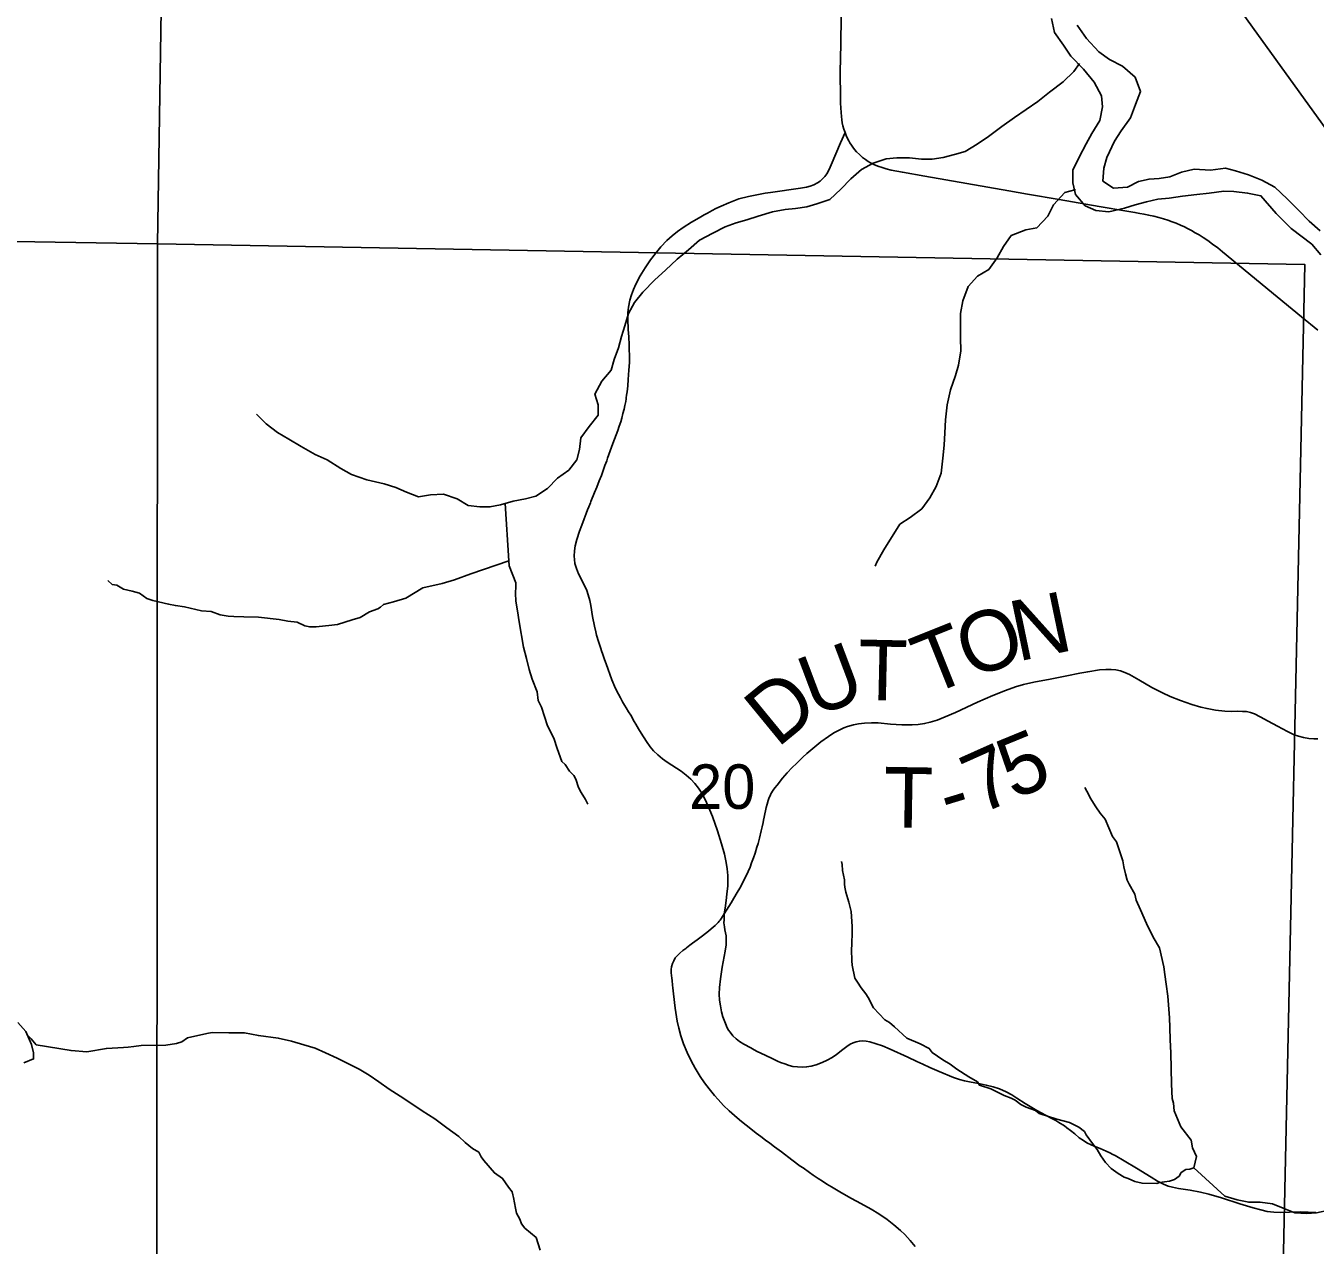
# Model space of a CAD drawing. Extents: x 0 to 34, y 0 to 22.
# Drawn here: x 5.516 to 6.729, y 14.708 to 15.855 of the extents above; entities that cross this region are included whole.
import ezdxf

# ---------------------------------------------------------------- set-up
doc = ezdxf.new("R2010")
doc.units = 0
for name, color, linetype in [('GM_X_Major_River', 7, 'Continuous'), ('GM_X_Minor_River', 7, 'Continuous'), ('GM_X_Rail_Line', 7, 'Continuous'), ('GM_X_Section', 7, 'Continuous'), ('GM_X_Section_Text', 7, 'Continuous'), ('GM_X_State_Route', 7, 'Continuous'), ('GM_X_Township_Road', 7, 'Continuous'), ('GM_X_Township_Road_Text', 7, 'Continuous')]:
    doc.layers.add(name, color=color, linetype=linetype)

msp = doc.modelspace()

# ---------------------------------------------------------------- linework, layer by layer
at = {"layer": 'GM_X_Major_River'}
for points in [[(6.4806, 15.8617), (6.4834, 15.8485), (6.4919, 15.8364), (6.4989, 15.8263), (6.5108, 15.8139), (6.5208, 15.8016), (6.5278, 15.7888), (6.5287, 15.7785), (6.5262, 15.7656), (6.5188, 15.7534), (6.5132, 15.7438), (6.5066, 15.7312), (6.5007, 15.719), (6.5009, 15.7069), (6.5033, 15.6959), (6.5125, 15.6854), (6.5224, 15.681), (6.5346, 15.6796), (6.5493, 15.6832), (6.5595, 15.6864), (6.5701, 15.6892), (6.5807, 15.6916), (6.5913, 15.6925), (6.6041, 15.6946), (6.6174, 15.6959), (6.6291, 15.6972), (6.6428, 15.6993), (6.6522, 15.699), (6.6652, 15.6973), (6.6777, 15.6948), (6.6922, 15.678), (6.7061, 15.6641), (6.7255, 15.6493), (6.7341, 15.6393)], [(6.7335, 15.6618), (6.7231, 15.6708), (6.7135, 15.6809), (6.7024, 15.6918), (6.6909, 15.703), (6.6786, 15.7096), (6.6661, 15.7144), (6.6539, 15.7184), (6.6444, 15.7209), (6.6304, 15.7188), (6.6148, 15.7198), (6.6031, 15.717), (6.5921, 15.7126), (6.5819, 15.711), (6.5725, 15.7105), (6.5626, 15.7084), (6.5521, 15.703), (6.5392, 15.7021), (6.5289, 15.7087), (6.5299, 15.7209), (6.5328, 15.7308), (6.5401, 15.7461), (6.5464, 15.756), (6.555, 15.7683), (6.5598, 15.7808), (6.5645, 15.793), (6.5594, 15.8063), (6.5475, 15.8167), (6.5353, 15.823), (6.5253, 15.8301), (6.5138, 15.8428), (6.5049, 15.8552)]]:
    msp.add_lwpolyline(points, dxfattribs=at)
at = {"layer": 'GM_X_Minor_River'}
for points in [[(6.5072, 15.8192), (6.5018, 15.8116), (6.4916, 15.8021), (6.4787, 15.7923), (6.4678, 15.7836), (6.4459, 15.7684), (6.4339, 15.7601), (6.4214, 15.7507), (6.4109, 15.7434), (6.3996, 15.7366), (6.3896, 15.7335), (6.3789, 15.7309), (6.3686, 15.7293), (6.3583, 15.7293), (6.347, 15.7305), (6.3352, 15.7305), (6.3253, 15.7297), (6.313, 15.7256), (6.3021, 15.7195), (6.2919, 15.7108), (6.2825, 15.7009), (6.2723, 15.6913), (6.2599, 15.6872), (6.2504, 15.6845), (6.24, 15.683), (6.2301, 15.6818), (6.2183, 15.6796), (6.2048, 15.6755), (6.1941, 15.6721), (6.1841, 15.6694), (6.1737, 15.6656), (6.1621, 15.6595), (6.1497, 15.6531), (6.1391, 15.644), (6.1286, 15.6353), (6.1176, 15.625), (6.1074, 15.6159), (6.0963, 15.6041), (6.0884, 15.5945), (6.0827, 15.5841), (6.0792, 15.5724), (6.0762, 15.5623), (6.0732, 15.5517), (6.0694, 15.5409), (6.0664, 15.5307), (6.0577, 15.5204), (6.0511, 15.5081), (6.0542, 15.4981), (6.0543, 15.4886), (6.0459, 15.4779), (6.0379, 15.4671), (6.0368, 15.4561), (6.0342, 15.4464), (6.0266, 15.4368), (6.0161, 15.4291), (6.0066, 15.4196), (5.9957, 15.4124), (5.9858, 15.4097), (5.9743, 15.4075), (5.9624, 15.4041), (5.9524, 15.4021), (5.9429, 15.4021), (5.932, 15.4036), (5.9215, 15.4097), (5.9088, 15.414), (5.8966, 15.4136), (5.8851, 15.4117), (5.8739, 15.4159), (5.8638, 15.4205), (5.8529, 15.4239), (5.8367, 15.4275), (5.822, 15.4326), (5.812, 15.4383), (5.7993, 15.4463), (5.7881, 15.4513), (5.7747, 15.459), (5.7632, 15.4658), (5.7524, 15.4723), (5.742, 15.4803), (5.7328, 15.4893)], [(6.5032, 15.7005), (6.5028, 15.7003), (6.4933, 15.698), (6.4826, 15.6862), (6.4773, 15.6757), (6.467, 15.6647), (6.4567, 15.6628), (6.4428, 15.6576), (6.4356, 15.6472), (6.4295, 15.6364), (6.4219, 15.6256), (6.4111, 15.6192), (6.4024, 15.6096), (6.3974, 15.5961), (6.395, 15.584), (6.395, 15.5726), (6.395, 15.5612), (6.3953, 15.5491), (6.3933, 15.5355), (6.3903, 15.5257), (6.3857, 15.5122), (6.3825, 15.4982), (6.3809, 15.4842), (6.3805, 15.4717), (6.3797, 15.4603), (6.3785, 15.4479), (6.3769, 15.4339), (6.3722, 15.4215), (6.3662, 15.4107), (6.3586, 15.4003), (6.3477, 15.3923), (6.3379, 15.3858), (6.323, 15.3617), (6.3165, 15.3501), (6.3149, 15.3464)], [(5.9668, 15.4055), (5.9701, 15.3515), (5.9706, 15.3466), (5.9766, 15.3307), (5.9766, 15.3273), (5.9764, 15.3209), (5.9769, 15.3136), (5.9782, 15.3045), (5.9799, 15.2939), (5.9841, 15.2701), (5.9869, 15.2595), (5.9894, 15.2493), (5.9922, 15.2402), (5.9969, 15.2281), (5.9978, 15.2201), (6.001, 15.2137), (6.0066, 15.1963), (6.0125, 15.1847), (6.0157, 15.1748), (6.0201, 15.1627), (6.0232, 15.1597), (6.0271, 15.1537), (6.0313, 15.1496), (6.0333, 15.1462), (6.0357, 15.1383), (6.0381, 15.1334), (6.0424, 15.127), (6.0444, 15.1224)], [(5.9701, 15.3515), (5.9343, 15.3392), (5.9192, 15.3336), (5.9075, 15.33), (5.8893, 15.3259), (5.8732, 15.3162), (5.8615, 15.313), (5.8524, 15.3105), (5.8494, 15.3078), (5.8468, 15.3063), (5.8392, 15.3035), (5.8302, 15.298), (5.8227, 15.296), (5.8091, 15.2916), (5.8007, 15.2907), (5.7916, 15.2898), (5.789, 15.2894), (5.7829, 15.2893), (5.7783, 15.2904), (5.7711, 15.2937), (5.7623, 15.2947), (5.754, 15.2961), (5.7346, 15.2984), (5.7209, 15.2986), (5.7114, 15.2992), (5.7061, 15.2995), (5.6985, 15.3005), (5.69, 15.3038), (5.6809, 15.3044), (5.6649, 15.308), (5.6565, 15.3094), (5.6501, 15.3108), (5.6352, 15.314), (5.6295, 15.3161), (5.6226, 15.321), (5.6157, 15.3228), (5.6077, 15.3249), (5.6012, 15.3286), (5.597, 15.3293), (5.593, 15.3328)], [(6.6147, 14.7804), (6.6172, 14.7911), (6.6133, 14.7994), (6.612, 14.8066), (6.6023, 14.819), (6.596, 14.8341), (6.5955, 14.8413), (6.5943, 14.8458), (6.5936, 14.8591), (6.5931, 14.8887), (6.5925, 14.9009), (6.592, 14.9123), (6.5918, 14.9214), (6.5903, 14.9419), (6.5886, 14.9532), (6.5873, 14.9623), (6.5864, 14.9695), (6.5823, 14.9873), (6.5764, 14.9975), (6.5701, 15.0103), (6.5646, 15.0231), (6.5603, 15.0322), (6.559, 15.0379), (6.5539, 15.0473), (6.552, 15.0511), (6.5504, 15.0571), (6.5487, 15.0635), (6.5479, 15.0692), (6.5419, 15.087), (6.538, 15.0922), (6.5312, 15.1085), (6.5266, 15.1141), (6.5223, 15.1201), (6.5172, 15.1284), (6.5157, 15.1314), (6.5141, 15.1348), (6.5121, 15.1382)], [(6.2833, 15.0685), (6.2837, 15.0658), (6.2842, 15.0601), (6.2859, 15.0514), (6.2859, 15.0472), (6.2864, 15.0446), (6.2872, 15.0397), (6.29, 15.0302), (6.2921, 15.0215), (6.2931, 15.0075), (6.2932, 15.0025), (6.293, 14.9904), (6.2927, 14.9858), (6.2929, 14.9752), (6.2933, 14.971), (6.2958, 14.9589), (6.2982, 14.9551), (6.3017, 14.9499), (6.3059, 14.9442), (6.3083, 14.9408), (6.3134, 14.931), (6.3238, 14.9198), (6.3284, 14.9172), (6.333, 14.9131), (6.3446, 14.9023), (6.3572, 14.8972), (6.3657, 14.8927), (6.3684, 14.889), (6.3784, 14.8819), (6.3853, 14.8778), (6.3918, 14.8734), (6.403, 14.866), (6.411, 14.8612), (6.413, 14.8581), (6.4236, 14.8549), (6.4363, 14.8486), (6.4428, 14.8461), (6.4466, 14.8442), (6.452, 14.8401), (6.457, 14.8376), (6.4658, 14.8343), (6.4692, 14.8317), (6.4856, 14.8262), (6.4978, 14.823), (6.5063, 14.8186), (6.5117, 14.8145), (6.5132, 14.8115), (6.5194, 14.8032), (6.5237, 14.7976), (6.5272, 14.7916), (6.5315, 14.7855), (6.5369, 14.7799), (6.5435, 14.7751), (6.5492, 14.7718), (6.5527, 14.7703), (6.5592, 14.7677), (6.566, 14.766), (6.5797, 14.7658), (6.5823, 14.7666), (6.5918, 14.7679), (6.5963, 14.7695), (6.6008, 14.7726), (6.6027, 14.776), (6.6072, 14.7788), (6.611, 14.7792), (6.6147, 14.7804)], [(5.514, 14.8793), (5.5231, 14.8829), (5.523, 14.8886), (5.521, 14.8965), (5.5158, 14.9086), (5.5081, 14.9172)], [(5.5171, 14.9056), (5.5209, 14.9018), (5.5255, 14.8962), (5.5583, 14.8907), (5.5731, 14.8894), (5.5916, 14.8927), (5.6076, 14.8937), (5.6121, 14.8938), (5.6174, 14.8946), (5.6242, 14.8955), (5.6474, 14.8959), (5.6576, 14.8975), (5.6625, 14.8991), (5.6678, 14.9026), (5.6859, 14.9067), (5.6912, 14.9076), (5.7068, 14.9074), (5.7216, 14.9073), (5.7345, 14.9048), (5.7532, 14.9025), (5.7658, 14.8996), (5.7772, 14.896), (5.7879, 14.8931), (5.7978, 14.8887), (5.8085, 14.8836), (5.8292, 14.8733), (5.8388, 14.8677), (5.8477, 14.8614), (5.8576, 14.8543), (5.868, 14.8477), (5.878, 14.8414), (5.8887, 14.8339), (5.9006, 14.8265), (5.9118, 14.818), (5.923, 14.8098), (5.9291, 14.8042), (5.9361, 14.7986), (5.9418, 14.7953), (5.9442, 14.7907), (5.9465, 14.7874), (5.9566, 14.7757), (5.9643, 14.7705), (5.9697, 14.7623), (5.9732, 14.7578), (5.974, 14.7551), (5.9744, 14.7525), (5.9765, 14.7426), (5.9773, 14.7377), (5.9805, 14.732), (5.9821, 14.7279), (5.9852, 14.7238), (5.996, 14.7148), (5.9996, 14.7031)], [(6.8402, 14.7225), (6.8294, 14.7267), (6.8189, 14.732), (6.8077, 14.7374), (6.798, 14.7427), (6.7878, 14.7449), (6.7757, 14.7453), (6.7642, 14.7435), (6.7524, 14.7416), (6.7417, 14.7405), (6.7302, 14.7382), (6.7207, 14.7374), (6.7097, 14.7382), (6.6988, 14.7424), (6.6887, 14.7465), (6.677, 14.7481), (6.6663, 14.7481), (6.6554, 14.7504), (6.6437, 14.7538), (6.6147, 14.7804)]]:
    msp.add_lwpolyline(points, dxfattribs=at)
at = {"layer": 'GM_X_Rail_Line'}
msp.add_lwpolyline([(6.5602, 16.0058), (6.7796, 15.7014)], dxfattribs=at)
at = {"layer": 'GM_X_Section'}
for points in [[(4.555, 16.6608), (5.6553, 16.6499), (5.6397, 15.6496), (4.5625, 15.6671), (4.5568, 16.3278)], [(4.5625, 15.6671), (5.6397, 15.6496), (5.6391, 14.6704), (4.5729, 14.6928), (4.5655, 15.3289)], [(5.6397, 15.6496), (6.7192, 15.6301), (6.698, 14.6582), (5.6391, 14.6704)]]:
    msp.add_lwpolyline(points, close=True, dxfattribs=at)
at = {"layer": 'GM_X_State_Route'}
msp.add_lwpolyline([(6.7312, 15.5684), (6.7158, 15.581), (6.6842, 15.607), (6.6611, 15.626), (6.6415, 15.6422), (6.6371, 15.6457), (6.6321, 15.6494), (6.6277, 15.6527), (6.6234, 15.6555), (6.6196, 15.658), (6.616, 15.6601), (6.6123, 15.6622), (6.6088, 15.664), (6.6057, 15.6656), (6.602, 15.6672), (6.598, 15.669), (6.5944, 15.6704), (6.5903, 15.6719), (6.5862, 15.6732), (6.5818, 15.6743), (6.577, 15.6755), (6.572, 15.6767), (6.5678, 15.6775), (6.5638, 15.6783), (6.5592, 15.6791), (6.5515, 15.6804), (6.5257, 15.6847), (6.4878, 15.6912), (6.4583, 15.6963), (6.4406, 15.6994), (6.3617, 15.7132), (6.3405, 15.7169), (6.3353, 15.7179), (6.3298, 15.719), (6.3253, 15.7201), (6.3214, 15.7213), (6.3172, 15.7227), (6.3136, 15.7244), (6.3105, 15.7259), (6.3083, 15.7272), (6.3057, 15.7289), (6.303, 15.7309), (6.3, 15.7336), (6.2974, 15.7361), (6.2955, 15.7384), (6.2939, 15.7404), (6.2925, 15.7423), (6.2911, 15.7445), (6.2899, 15.7466), (6.2888, 15.7487), (6.2876, 15.7515), (6.2865, 15.7542), (6.2854, 15.7575), (6.2845, 15.7605), (6.2839, 15.7634), (6.2834, 15.7663), (6.2831, 15.7694), (6.2827, 15.7731), (6.2824, 15.7774), (6.2822, 15.7818), (6.2821, 15.7866), (6.282, 15.8114), (6.2824, 15.8375), (6.2828, 15.8635)], dxfattribs=at)
at = {"layer": 'GM_X_Township_Road'}
for points in [[(6.1729, 15.0193), (6.1737, 15.0248), (6.1746, 15.0319), (6.1754, 15.038), (6.1761, 15.0456), (6.1761, 15.0555), (6.1757, 15.0616), (6.1747, 15.0677), (6.173, 15.0756), (6.1704, 15.0851), (6.1664, 15.0975), (6.1617, 15.111), (6.1578, 15.1208), (6.1547, 15.1276), (6.1517, 15.133), (6.1486, 15.1377), (6.1451, 15.142), (6.1413, 15.1461), (6.1371, 15.1498), (6.1322, 15.1535), (6.1192, 15.162), (6.1146, 15.1653), (6.1104, 15.1688), (6.1064, 15.1727), (6.1032, 15.1765), (6.0996, 15.1814), (6.0947, 15.1892), (6.0922, 15.1935), (6.0897, 15.1977), (6.0882, 15.2004), (6.0848, 15.2062), (6.0829, 15.2094), (6.0807, 15.2131), (6.0791, 15.2157), (6.0772, 15.2189), (6.0751, 15.2226), (6.0733, 15.2259), (6.0706, 15.2314), (6.0671, 15.2394), (6.0616, 15.2545), (6.0602, 15.2586), (6.0586, 15.2632), (6.0574, 15.2667), (6.0566, 15.2691), (6.0545, 15.2756), (6.0528, 15.2815), (6.052, 15.2845), (6.0508, 15.2899), (6.049, 15.299), (6.0474, 15.3094), (6.0464, 15.3141), (6.0449, 15.3194), (6.0434, 15.3235), (6.0417, 15.3275), (6.0358, 15.3391), (6.0337, 15.3443), (6.0324, 15.349), (6.0319, 15.3527), (6.0317, 15.3558), (6.032, 15.3607), (6.0327, 15.3656), (6.0342, 15.3716), (6.0366, 15.3793), (6.0387, 15.385), (6.0409, 15.3908), (6.0429, 15.3959), (6.0442, 15.3993), (6.0454, 15.4022), (6.047, 15.4061), (6.0474, 15.4072), (6.0509, 15.4158), (6.053, 15.4208), (6.0552, 15.4266), (6.0573, 15.4317), (6.0583, 15.4346), (6.0606, 15.441), (6.0623, 15.4456), (6.0631, 15.448), (6.0681, 15.4619), (6.0696, 15.4659), (6.0711, 15.47), (6.0726, 15.474), (6.074, 15.4781), (6.0754, 15.4822), (6.0764, 15.4857), (6.0775, 15.4899), (6.0786, 15.4941), (6.0794, 15.4977), (6.0801, 15.5013), (6.0804, 15.5037), (6.0806, 15.5049), (6.0809, 15.5073), (6.0814, 15.5103), (6.082, 15.5159), (6.0825, 15.522), (6.0832, 15.5307), (6.0836, 15.5381), (6.0836, 15.5437), (6.0835, 15.5511), (6.0834, 15.5548), (6.0833, 15.5572), (6.0832, 15.5597), (6.083, 15.5622), (6.0825, 15.569), (6.0821, 15.5789), (6.0821, 15.5851), (6.0827, 15.59), (6.0841, 15.5967), (6.0855, 15.6015), (6.0874, 15.6067), (6.0897, 15.6118), (6.0938, 15.6195), (6.0983, 15.6269), (6.1035, 15.6347), (6.108, 15.6406), (6.1133, 15.6467), (6.1188, 15.6526), (6.1238, 15.6572), (6.1287, 15.6611), (6.1342, 15.6651), (6.1421, 15.67), (6.1469, 15.6729), (6.1507, 15.6751), (6.1539, 15.6768), (6.1572, 15.6786), (6.1616, 15.681), (6.1649, 15.6827), (6.1699, 15.6851), (6.1773, 15.6883), (6.1866, 15.6918), (6.1956, 15.6941), (6.2035, 15.6958), (6.2114, 15.6973), (6.2163, 15.6979), (6.2446, 15.702), (6.2501, 15.703), (6.2537, 15.7039), (6.2572, 15.7052), (6.2605, 15.707), (6.263, 15.7087), (6.2654, 15.7108), (6.2675, 15.713), (6.2693, 15.7156), (6.2714, 15.7194), (6.2735, 15.7239), (6.2777, 15.7342), (6.2822, 15.7445), (6.2865, 15.7542)], [(6.1729, 15.0193), (6.1773, 15.0263), (6.1794, 15.0298), (6.1819, 15.0341), (6.1851, 15.0393), (6.1875, 15.0434), (6.1911, 15.0501), (6.1953, 15.0591), (6.1972, 15.0633), (6.1986, 15.0672), (6.2005, 15.0719), (6.2019, 15.0765), (6.2036, 15.082), (6.2046, 15.0855), (6.2059, 15.0905), (6.2077, 15.0975), (6.2085, 15.1012), (6.2094, 15.1054), (6.2098, 15.1074), (6.2105, 15.1102), (6.2111, 15.1134), (6.2117, 15.1163), (6.2123, 15.1193), (6.2131, 15.1226), (6.2141, 15.1259), (6.2152, 15.1287), (6.2159, 15.1305), (6.2168, 15.1321), (6.2188, 15.1356), (6.2205, 15.1379), (6.2225, 15.1405), (6.2275, 15.1469), (6.2319, 15.1521), (6.2367, 15.1569), (6.2408, 15.1608), (6.2469, 15.1667), (6.2506, 15.1701), (6.258, 15.1765), (6.2638, 15.1812), (6.2708, 15.1863), (6.276, 15.1896), (6.2815, 15.1926), (6.2854, 15.1944), (6.2889, 15.1957), (6.2943, 15.1972), (6.2992, 15.1981), (6.3047, 15.1987), (6.3115, 15.199), (6.3177, 15.1989), (6.3294, 15.1979), (6.3398, 15.1972), (6.3459, 15.197), (6.3496, 15.197), (6.3552, 15.1974), (6.3613, 15.1984), (6.3667, 15.1996), (6.3732, 15.2017), (6.3807, 15.2046), (6.3904, 15.2088), (6.4112, 15.2184), (6.4254, 15.2246), (6.4374, 15.2295), (6.4468, 15.2328), (6.4545, 15.235), (6.4642, 15.2373), (6.4795, 15.2402), (6.4953, 15.2434), (6.5075, 15.2458), (6.5148, 15.2471), (6.5258, 15.2488), (6.532, 15.2493), (6.537, 15.2493), (6.5413, 15.2488), (6.5455, 15.2479), (6.5496, 15.2465), (6.5542, 15.2444), (6.5628, 15.2396), (6.5752, 15.2324), (6.5851, 15.2273), (6.5924, 15.2239), (6.6022, 15.22), (6.6128, 15.2162), (6.6211, 15.2138), (6.6271, 15.2124), (6.6351, 15.211), (6.6437, 15.21), (6.65, 15.2098), (6.6558, 15.2099), (6.6604, 15.2098), (6.6641, 15.2097), (6.6679, 15.2089), (6.6716, 15.2075), (6.6772, 15.2047), (6.6846, 15.2007), (6.6932, 15.1959), (6.7029, 15.1908), (6.709, 15.1879), (6.7131, 15.1864), (6.7178, 15.1851), (6.7227, 15.1844), (6.7276, 15.184), (6.7314, 15.1841)], [(6.1366, 14.9868), (6.1374, 14.9875), (6.1404, 14.9898), (6.143, 14.9917), (6.1452, 14.9933), (6.1475, 14.995), (6.1498, 14.9967), (6.1524, 14.9988), (6.1581, 15.0032), (6.1605, 15.0051), (6.1625, 15.0068), (6.1642, 15.0083), (6.1655, 15.0097), (6.167, 15.0112), (6.168, 15.0124), (6.169, 15.0135), (6.1703, 15.0154), (6.1729, 15.0193)], [(6.7295, 14.7383), (6.7221, 14.7388), (6.7153, 14.7389), (6.7047, 14.7386), (6.696, 14.7384), (6.6898, 14.7388), (6.6837, 14.7395), (6.6776, 14.7408), (6.6704, 14.7427), (6.6579, 14.7466), (6.6408, 14.7523), (6.6289, 14.7557), (6.621, 14.7575), (6.6113, 14.7594), (6.6002, 14.761), (6.5947, 14.7621), (6.5906, 14.7633), (6.586, 14.7651), (6.5804, 14.7679), (6.5746, 14.7715), (6.5608, 14.78), (6.5491, 14.787), (6.5405, 14.792), (6.5383, 14.7931), (6.5356, 14.7946), (6.5322, 14.7962), (6.5265, 14.7985), (6.5224, 14.8001), (6.5179, 14.8022), (6.5141, 14.8041), (6.5109, 14.806), (6.5069, 14.8088), (6.5026, 14.8125), (6.4987, 14.8155), (6.4953, 14.8181), (6.4928, 14.8199), (6.4877, 14.8232), (6.4848, 14.8249), (6.4818, 14.8264), (6.4751, 14.83), (6.471, 14.8321), (6.4668, 14.8344), (6.4621, 14.8371), (6.4558, 14.8411), (6.4482, 14.8461), (6.4433, 14.8491), (6.438, 14.852), (6.4317, 14.8546), (6.4258, 14.8566), (6.4193, 14.8583), (6.4121, 14.8597), (6.4037, 14.8612), (6.399, 14.8622), (6.3943, 14.8634), (6.3886, 14.8654), (6.3749, 14.8712), (6.3664, 14.8749), (6.3596, 14.8779), (6.354, 14.8805), (6.3457, 14.8845), (6.3289, 14.8921), (6.3216, 14.8953), (6.3158, 14.8972), (6.3098, 14.8989), (6.3062, 14.8996), (6.3031, 14.8999), (6.3, 14.8997), (6.2969, 14.8991), (6.294, 14.8981), (6.2913, 14.8967), (6.2882, 14.8946), (6.2845, 14.8917), (6.2785, 14.8869), (6.2745, 14.8842), (6.2698, 14.8816), (6.2649, 14.8794), (6.2592, 14.8774), (6.2545, 14.8762), (6.2503, 14.8754), (6.246, 14.8752), (6.2417, 14.8753), (6.2374, 14.8759), (6.2338, 14.8768), (6.2297, 14.8782), (6.2259, 14.8795), (6.2228, 14.8809), (6.2172, 14.8835), (6.2072, 14.8884), (6.2038, 14.89), (6.2011, 14.8915), (6.1978, 14.8932), (6.1913, 14.8968), (6.1871, 14.8994), (6.1841, 14.9017), (6.181, 14.9046), (6.1783, 14.908), (6.1769, 14.91), (6.1757, 14.9122), (6.1739, 14.9161), (6.1716, 14.9225), (6.1703, 14.9273), (6.1692, 14.9328), (6.1685, 14.9383), (6.1682, 14.9439), (6.1684, 14.9501), (6.1693, 14.9581), (6.171, 14.9691), (6.1737, 14.9842), (6.1745, 14.9903), (6.1747, 14.9945), (6.1745, 14.9987), (6.1734, 15.0044), (6.173, 15.0071), (6.1726, 15.0108), (6.1727, 15.0137), (6.1729, 15.0193)], [(6.3524, 14.7065), (6.3477, 14.7122), (6.3426, 14.7177), (6.3386, 14.7216), (6.3325, 14.7269), (6.3261, 14.7318), (6.3184, 14.7371), (6.311, 14.7416), (6.3012, 14.747), (6.2925, 14.7517), (6.2833, 14.7568), (6.2737, 14.7625), (6.2694, 14.765), (6.2653, 14.7678), (6.2612, 14.7704), (6.2566, 14.7736), (6.253, 14.776), (6.247, 14.7803), (6.2444, 14.7821), (6.2365, 14.7879), (6.2266, 14.7954), (6.2201, 14.8002), (6.2157, 14.8035), (6.2117, 14.8065), (6.2073, 14.8099), (6.2028, 14.8132), (6.1979, 14.8171), (6.1892, 14.824), (6.1849, 14.8276), (6.1774, 14.8341), (6.1721, 14.8392), (6.1671, 14.8447), (6.1638, 14.8484), (6.1587, 14.8546), (6.1542, 14.8605), (6.1503, 14.8662), (6.1454, 14.8741), (6.1416, 14.8812), (6.1379, 14.889), (6.1346, 14.8971), (6.132, 14.9047), (6.13, 14.9119), (6.1286, 14.9185), (6.1267, 14.9307), (6.125, 14.9442), (6.1244, 14.9498), (6.1242, 14.9522), (6.1237, 14.9566), (6.1235, 14.959), (6.123, 14.964), (6.123, 14.9671), (6.1233, 14.9695), (6.1241, 14.9725), (6.1253, 14.9753), (6.1268, 14.9779), (6.1288, 14.9803), (6.1311, 14.9824), (6.134, 14.9849), (6.1366, 14.9868)]]:
    msp.add_lwpolyline(points, dxfattribs=at)

# ---------------------------------------------------------------- texts
at = {"layer": 'GM_X_Section_Text'}
msp.add_text('20', height=0.04186, rotation=0, dxfattribs=at).set_placement((6.1398, 15.1181))
at = {"layer": 'GM_X_Township_Road_Text'}
for s, rotation, p in [('N', 11.7536, (6.4489, 15.2566)), ('O', 20.3233, (6.4042, 15.2398)), ('T', 21.8087, (6.3651, 15.2242)), ('U', 20.6784, (6.2571, 15.204)), ('T', 358.7442, (6.2982, 15.2207)), ('D', 39.3835, (6.2226, 15.1747)), ('5', 22.3, (6.4448, 15.1264)), ('7', 24.0951, (6.4133, 15.1123)), ('T', 359.0529, (6.3225, 15.1009)), ('-', 16.9195, (6.3838, 15.1029))]:
    msp.add_text(s, height=0.0568, rotation=rotation, dxfattribs=at).set_placement(p)

doc.saveas('drawing.dxf')
